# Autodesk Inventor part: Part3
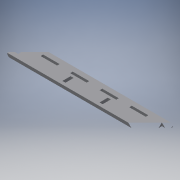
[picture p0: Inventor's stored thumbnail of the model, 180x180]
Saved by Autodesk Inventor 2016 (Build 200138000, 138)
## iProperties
Created: 2017-06
Part Number: Part3
Material: Generic
Document SubType Name: Modeling
Designer: laboratorioesan
Density: 1 g/cm^3
Appearance: Default
Author: laboratorioesan
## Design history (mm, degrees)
sketch "Sketch1"
  geometry: L1 (0, -27.5)-(0, -102.5) reference; L2 (0, -102.5)-(18.5, -102.5) reference; L3 (18.5, -27.5)-(18.5, -102.5) reference; L4 (0, -27.5)-(18.5, -27.5) reference; L5 (0, 0)-(18.5, 0) reference; L6 (0, -130)-(18.5, -130) reference; L7 (-20, 0)-(857, 0); L8 (857, 0)-(857, -130); L9 (857, -130)-(-20, -130); L10 (-20, -130)-(-20, 0); L11 (0, -27.5)-(18.5, -27.5); L12 (18.5, -27.5)-(18.5, -102.5); L13 (18.5, -102.5)-(0, -102.5); L14 (0, -102.5)-(0, -27.5); L15 (818.5, -27.5)-(837, -27.5); L16 (837, -27.5)-(837, -102.5); L17 (837, -102.5)-(818.5, -102.5); L18 (818.5, -102.5)-(818.5, -27.5)
  constraints: 24 end point, 6 parallel, 3 horizontal, 3 perpendicular, 2 collinear, 2 horizontal alignment, 2 point on line
  dimensions: "d0" = 20 horizontal distance of L7.start L1.start; "d1" = 20 horizontal distance of L8.end L16.end; "d2" = 800 distance of L17.end L2.end
extrude "Extrusion1" new body sketch "Sketch1" distance "d3" = 18.5; taper "d4" = 0 deg
sketch "Sketch2"
  geometry: L1 (837, -102.5)-(837, -27.5) reference; L2 (837, -27.5)-(818.5, -27.5) reference; L3 (818.5, -27.5)-(818.5, -102.5) reference; L4 (818.5, -102.5)-(837, -102.5) reference; L5 (18.5, -27.5)-(0, -27.5) reference; L6 (0, -27.5)-(0, -102.5) reference; L7 (0, -102.5)-(18.5, -102.5) reference; L8 (18.5, -102.5)-(18.5, -27.5) reference; L9 (-20, 0)-(857, 0) reference; L10 (857, 0)-(857, -130) reference; L11 (857, -130)-(-20, -130) reference; L12 (-20, -130)-(-20, 0) reference; L13 (738.5, -45.5)-(638.5, -45.5); L14 (638.5, -45.5)-(638.5, -30); L15 (638.5, -30)-(738.5, -30); L16 (738.5, -30)-(738.5, -45.5); L17 (558.5, -45.5)-(458.5, -45.5); L18 (458.5, -45.5)-(458.5, -30); L19 (458.5, -30)-(558.5, -30); L20 (558.5, -30)-(558.5, -45.5); L21 (378.5, -45.5)-(278.5, -45.5); L22 (278.5, -45.5)-(278.5, -30); L23 (278.5, -30)-(378.5, -30); L24 (378.5, -30)-(378.5, -45.5); L25 (198.5, -45.5)-(98.5, -45.5); L26 (98.5, -45.5)-(98.5, -30); L27 (98.5, -30)-(198.5, -30); L28 (198.5, -30)-(198.5, -45.5); 1 further point
  constraints: 32 end point, 8 parallel, 6 point on line, 4 horizontal, 4 perpendicular, 3 collinear
  dimensions: "d5" = 15.5 distance of L25.end L26.end; "d6" = 100 distance of L25.start L25.end; "d7" = 80 distance of L21.end L25.start; "d8" = 80 distance of L17.end L21.start; "d9" = 80 distance of L13.end L17.start; "d10" = 30 vertical distance of L9.end L15.end; "d11" = 80 horizontal distance of L2.end L13.start
extrude "Extrusion2" cut sketch "Sketch2" distance "d12" = 18.5; taper "d13" = 0 deg
sketch "Sketch3"
  geometry: L1 (-296, -130.5)-(-296, -185.5) reference; L2 (-296, -185.5)-(-314.5, -185.5) reference; L3 (-314.5, -185.5)-(-314.5, -130.5) reference; L4 (-314.5, -130.5)-(-296, -130.5) reference; L5 (-522.5, -130.5)-(-522.5, -185.5) reference; L6 (-541, -185.5)-(-541, -130.5) reference; L7 (-522.5, -185.5)-(-541, -185.5) reference; L8 (-541, -130.5)-(-522.5, -130.5) reference; L9 (-296, -110.5)-(-314.5, -110.5); L10 (-314.5, -110.5)-(-314.5, -60.5); L11 (-314.5, -60.5)-(-296, -60.5); L12 (-296, -60.5)-(-296, -110.5); L13 (-522.5, -110.5)-(-541, -110.5); L14 (-541, -110.5)-(-541, -60.5); L15 (-541, -60.5)-(-522.5, -60.5); L16 (-522.5, -60.5)-(-522.5, -110.5); 1 further point
  constraints: 32 end point, 6 horizontal, 4 parallel, 4 vertical, 2 perpendicular, 8 other
  dimensions: "d14" = 50 distance of L9.end L10.end; "d15" = 20 distance of L9.start L1.start
extrude "Extrusion3" cut sketch "Sketch3" distance "d16" = 18.5; taper "d17" = 0 deg
body "Solid1"
node "Reference1"
node "Reference2"
node "Reference3"
node "Projected Loop1"
